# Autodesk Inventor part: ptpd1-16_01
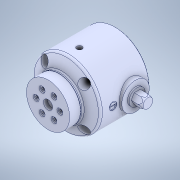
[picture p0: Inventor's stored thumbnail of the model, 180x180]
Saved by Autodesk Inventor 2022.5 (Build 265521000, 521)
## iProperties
Created: 2023-04
Part Number: ptpd1-16_01
Material: Generic
Document SubType Name: Modeling
Designer: ImaoCorp
Density: 1 g/cm^3
Appearance: Default
Author: ImaoCorp
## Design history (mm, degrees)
feature "ptpd1-16_01"
node "ソリッド1"
